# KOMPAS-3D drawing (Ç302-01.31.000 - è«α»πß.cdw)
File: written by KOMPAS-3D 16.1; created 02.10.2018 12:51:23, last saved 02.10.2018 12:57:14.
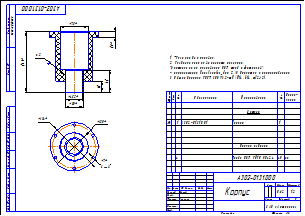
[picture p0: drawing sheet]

Sheet 1: A3, landscape

Title block, sheet 1: name: Корпус; designation: А302-01.31.000; mass: 0,62; scale: 1:2; sheets: 1; organisation: ЗАО «Астерион»; sheet format: A3; stored path: \\192.168.87.28\Konstructor_doc\Мембранные насосы\Мембранный электропривод\А302-00.00.000 - ASTRA-302 (МЭ200)\3Д ПВХ\А302-01.31.000 - Корпус.cdw; drawn by: Милов; technical control: Лучихин

Views: Вид 1, Местный разрез 1, Спереди, Проекционный вид 2
Referenced files in \\192.168.87.28\Konstructor_doc\Мембранные насосы\Мембранный электропривод\А302-00.00.000 - ASTRA-302 (МЭ200)\3Д ПВХ\Отработка\: Труба ПВХ PN10 50х2,4.m3d
Referenced files in \\192.168.87.28\Konstructor_doc\Мембранные насосы\Мембранный электропривод\А302-00.00.000 - ASTRA-302 (МЭ200)\3Д ПВХ\: А302-01.31.001 - Корпус.m3d, А302-01.31.000 - Корпус.a3d
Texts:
  *Размеры для справок.
  Разделку кромок выполнить согласно:
  "Инструкция по склеиванию ПВХ труб и фитингов".
  - расположение Konstructor_doc Z:\5 Оснастка и приспособления
  Общие допуски ГОСТ 30893.2-mK (H14, h14,  t2/2).
  Труба ПВХ PN10 50х2,4
Dimensions and other numbers on the sheet: 45,2; 50; 78; 167; 61; 31; 2; 15; 120; 7; 6 отв.; 134; 1:2; 1; 0,62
